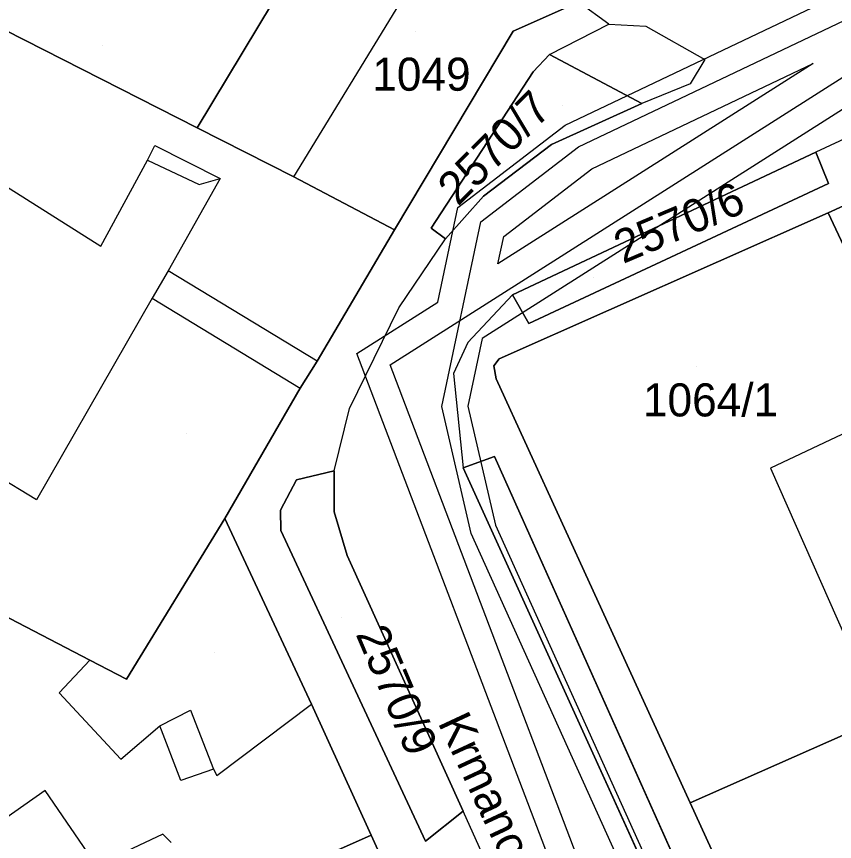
# Model space of a CAD drawing. Extents: x -263423 to -261326, y -1240067 to -1237864.
# Drawn here: x -262616.67 to -262567.2, y -1239776.12 to -1239726.22 of the extents above; entities that cross this region are included whole.
import ezdxf

# ---------------------------------------------------------------- set-up
doc = ezdxf.new("R2010")
doc.units = 0
for name, color, linetype in [('body_kn', 7, 'Continuous'), ('kladpar_druhypozemkov', 7, 'Continuous'), ('kladpar_hranice', 7, 'Continuous'), ('kladpar_parcelnecisla', 7, 'Continuous'), ('kladpar_plochy', 7, 'Continuous'), ('popisy', 7, 'Continuous'), ('tarchy_linie', 7, 'Continuous'), ('zappar_hrandruhpozemk', 7, 'Continuous')]:
    doc.layers.add(name, color=color, linetype=linetype)

msp = doc.modelspace()

# ---------------------------------------------------------------- linework, layer by layer
at = {"layer": 'body_kn'}
for p, q in [((-262580.85, -1239726.69), (-262580.85, -1239726.69)), ((-262586.63, -1239727.11), (-262586.63, -1239727.11)), ((-262578.61, -1239726.8), (-262578.61, -1239726.8)), ((-262584.43, -1239728.52), (-262584.43, -1239728.52)), ((-262584.43, -1239728.52), (-262584.43, -1239728.52)), ((-262575.04, -1239728.82), (-262575.04, -1239728.82)), ((-262568.48, -1239729.06), (-262568.48, -1239729.06)), ((-262585.42, -1239729.57), (-262585.42, -1239729.57)), ((-262575.93, -1239730.29), (-262575.93, -1239730.29)), ((-262578.84, -1239731.48), (-262578.84, -1239731.48)), ((-262605.75, -1239732.95), (-262605.75, -1239732.95)), ((-262583.49, -1239732.79), (-262583.49, -1239732.79)), ((-262608.3, -1239734.02), (-262608.3, -1239734.02)), ((-262584.32, -1239733.97), (-262584.32, -1239733.97)), ((-262582.68, -1239734.11), (-262582.68, -1239734.11)), ((-262568.33, -1239734.43), (-262568.33, -1239734.43)), ((-262608.75, -1239734.91), (-262608.75, -1239734.91)), ((-262608.75, -1239734.91), (-262608.75, -1239734.91)), ((-262581.87, -1239735.43), (-262581.87, -1239735.43)), ((-262604.36, -1239736.02), (-262604.36, -1239736.02)), ((-262599.9, -1239735.91), (-262599.9, -1239735.91)), ((-262599.9, -1239735.91), (-262599.9, -1239735.91)), ((-262605.63, -1239736.39), (-262605.63, -1239736.39)), ((-262567.56, -1239736.33), (-262567.56, -1239736.33)), ((-262588.43, -1239737.08), (-262588.43, -1239737.08)), ((-262589.98, -1239737.78), (-262589.98, -1239737.78)), ((-262567.58, -1239738.09), (-262567.58, -1239738.09)), ((-262567.58, -1239738.09), (-262567.58, -1239738.09)), ((-262588.59, -1239738.65), (-262588.59, -1239738.65)), ((-262593.8, -1239739.12), (-262593.8, -1239739.12)), ((-262591.59, -1239739.02), (-262591.59, -1239739.02)), ((-262590.73, -1239739.67), (-262590.73, -1239739.67)), ((-262587.2, -1239739.52), (-262587.2, -1239739.52)), ((-262611.57, -1239740.12), (-262611.57, -1239740.12)), ((-262587.55, -1239741.18), (-262587.55, -1239741.18)), ((-262587.55, -1239741.18), (-262587.55, -1239741.18)), ((-262607.5, -1239741.61), (-262607.5, -1239741.61)), ((-262586.67, -1239743.05), (-262586.67, -1239743.05)), ((-262586.67, -1239743.05), (-262586.67, -1239743.05)), ((-262608.46, -1239743.26), (-262608.46, -1239743.26)), ((-262591.19, -1239743.49), (-262591.19, -1239743.49)), ((-262593.54, -1239743.84), (-262593.54, -1239743.84)), ((-262585.68, -1239744.78), (-262585.68, -1239744.78)), ((-262588.51, -1239745.7), (-262588.51, -1239745.7)), ((-262589.37, -1239745.93), (-262589.37, -1239745.93)), ((-262596.09, -1239746.61), (-262596.09, -1239746.61)), ((-262598.48, -1239747.06), (-262598.48, -1239747.06)), ((-262598.48, -1239747.06), (-262598.48, -1239747.06)), ((-262587.47, -1239746.92), (-262587.47, -1239746.92)), ((-262594.07, -1239747.28), (-262594.07, -1239747.28)), ((-262587.79, -1239747.36), (-262587.79, -1239747.36)), ((-262590.24, -1239747.81), (-262590.24, -1239747.81)), ((-262587.66, -1239748.13), (-262587.66, -1239748.13)), ((-262599.51, -1239748.71), (-262599.51, -1239748.71)), ((-262596.53, -1239749.94), (-262596.53, -1239749.94)), ((-262590.95, -1239749.81), (-262590.95, -1239749.81)), ((-262589.37, -1239749.79), (-262589.37, -1239749.79)), ((-262587.75, -1239752.83), (-262587.75, -1239752.83)), ((-262597.45, -1239753.7), (-262597.45, -1239753.7)), ((-262597.45, -1239753.7), (-262597.45, -1239753.7)), ((-262589.66, -1239753.52), (-262589.66, -1239753.52)), ((-262589.66, -1239753.52), (-262589.66, -1239753.52)), ((-262571.07, -1239753.55), (-262571.07, -1239753.55)), ((-262599.73, -1239754.24), (-262599.73, -1239754.24)), ((-262615.45, -1239755.46), (-262615.45, -1239755.46)), ((-262600.71, -1239756.09), (-262600.71, -1239756.09)), ((-262597.46, -1239756.18), (-262597.46, -1239756.18)), ((-262604.06, -1239756.59), (-262604.06, -1239756.59)), ((-262587.69, -1239756.99), (-262587.69, -1239756.99)), ((-262600.68, -1239757.32), (-262600.68, -1239757.32)), ((-262589.16, -1239757.49), (-262589.16, -1239757.49)), ((-262596.66, -1239758.83), (-262596.66, -1239758.83)), ((-262612.24, -1239765.15), (-262612.24, -1239765.15)), ((-262612.24, -1239765.15), (-262612.24, -1239765.15)), ((-262610.01, -1239766.31), (-262610.01, -1239766.31)), ((-262614.09, -1239767.12), (-262614.09, -1239767.12)), ((-262606.14, -1239768.17), (-262606.14, -1239768.17)), ((-262598.82, -1239767.82), (-262598.82, -1239767.82)), ((-262607.99, -1239769.12), (-262607.99, -1239769.12)), ((-262610.35, -1239771.15), (-262610.35, -1239771.15)), ((-262604.75, -1239771.75), (-262604.75, -1239771.75)), ((-262604.75, -1239771.75), (-262604.75, -1239771.75)), ((-262604.56, -1239772.13), (-262604.56, -1239772.13)), ((-262606.73, -1239772.44), (-262606.73, -1239772.44)), ((-262614.94, -1239773.04), (-262614.94, -1239773.04)), ((-262575.93, -1239773.78), (-262575.93, -1239773.78)), ((-262589.66, -1239774.29), (-262589.66, -1239774.29)), ((-262607.82, -1239775.68), (-262607.82, -1239775.68)), ((-262595.22, -1239775.74), (-262595.22, -1239775.74)), ((-262591.93, -1239776.1), (-262591.93, -1239776.1))]:
    msp.add_line(p, q, dxfattribs=at)
at = {"layer": 'kladpar_druhypozemkov'}
for p, q in [((-262592.52, -1239727.11), (-262592.52, -1239727.11)), ((-262611.48, -1239727.97), (-262611.48, -1239727.97)), ((-262583.67, -1239731.6), (-262583.67, -1239731.6)), ((-262581.79, -1239741.99), (-262581.79, -1239741.99)), ((-262575.52, -1239747.41), (-262575.52, -1239747.41)), ((-262606.38, -1239751.47), (-262606.38, -1239751.47)), ((-262596.99, -1239762.57), (-262596.99, -1239762.57)), ((-262604.68, -1239764.67), (-262604.68, -1239764.67)), ((-262578.7, -1239776.06), (-262578.7, -1239776.06))]:
    msp.add_line(p, q, dxfattribs=at)
at = {"layer": 'kladpar_hranice'}
for points in [[(-262451.68, -1239667.17), (-262451.23, -1239668.28), (-262460.7, -1239672.48), (-262459.45, -1239675.31), (-262450.08, -1239671.04), (-262449.88, -1239671.51), (-262445.64, -1239681.71), (-262444.85, -1239683.55), (-262470.85, -1239694.98), (-262473.53, -1239696.16), (-262490.19, -1239703.49), (-262516.65, -1239715.13), (-262520.79, -1239716.96), (-262535.01, -1239723.27), (-262548.9, -1239729.45), (-262556.42, -1239732.92), (-262556.62, -1239733.02), (-262559.29, -1239734.31), (-262559.85, -1239734.56), (-262567.58, -1239738.09)], [(-262586.63, -1239727.11), (-262582.68, -1239725.35), (-262578.09, -1239723.27), (-262558.66, -1239714.51), (-262552.49, -1239711.73), (-262529.26, -1239701.26), (-262527.35, -1239700.25), (-262522.32, -1239697.89), (-262517.4, -1239695.64)], [(-262596.33, -1239717.39), (-262598, -1239720.19), (-262600.24, -1239723.81), (-262605.75, -1239732.95), (-262622.01, -1239724.66), (-262626.2, -1239722.48), (-262626.46, -1239722.8), (-262634.27, -1239717.98), (-262626.07, -1239705.15), (-262622.39, -1239708.04), (-262619.83, -1239704.16), (-262596.33, -1239717.39)], [(-262591.12, -1239720.34), (-262583.18, -1239724.9), (-262582.68, -1239725.35), (-262586.63, -1239727.11), (-262593.8, -1239739.12), (-262599.9, -1239735.91), (-262605.75, -1239732.95), (-262600.24, -1239723.81), (-262598, -1239720.19), (-262596.33, -1239717.39), (-262591.12, -1239720.34)], [(-262634.27, -1239717.98), (-262626.46, -1239722.8), (-262626.2, -1239722.48), (-262622.01, -1239724.66), (-262605.75, -1239732.95), (-262599.9, -1239735.91), (-262593.8, -1239739.12), (-262598.48, -1239747.06), (-262599.51, -1239748.71), (-262604.06, -1239756.59), (-262610.01, -1239766.31), (-262612.24, -1239765.15), (-262619.03, -1239761.62), (-262624.31, -1239758.73), (-262639.86, -1239747.9), (-262649, -1239741.36), (-262648.81, -1239741.1), (-262648.49, -1239740.53), (-262643.94, -1239732.97), (-262641, -1239728.65), (-262638.63, -1239724.97), (-262634.27, -1239717.98)], [(-262587.66, -1239748.13), (-262575.93, -1239773.78), (-262560.41, -1239807.74), (-262562.89, -1239808.81), (-262563.41, -1239809.03), (-262563, -1239808.14), (-262566.99, -1239799.19), (-262568.5, -1239800.1), (-262565.39, -1239806.94), (-262563.41, -1239809.03), (-262572.52, -1239812.91), (-262586.96, -1239780.25), (-262589.76, -1239780.87), (-262575.06, -1239814.02), (-262575.26, -1239814.11), (-262577.3, -1239815.05), (-262592.7, -1239781.29), (-262595.22, -1239775.74), (-262598.82, -1239767.82), (-262604.06, -1239756.59), (-262599.51, -1239748.71), (-262598.48, -1239747.06), (-262593.8, -1239739.12), (-262586.63, -1239727.11)], [(-262584.43, -1239728.52), (-262585.42, -1239729.57), (-262591.59, -1239739.02), (-262590.73, -1239739.67), (-262588.43, -1239737.08), (-262584.32, -1239733.97), (-262578.84, -1239731.48), (-262584.43, -1239728.52)], [(-262584.43, -1239728.52), (-262578.84, -1239731.48), (-262584.32, -1239733.97), (-262588.43, -1239737.08), (-262590.73, -1239739.67), (-262591.59, -1239739.02), (-262585.42, -1239729.57), (-262584.43, -1239728.52)], [(-262548.9, -1239729.45), (-262543.84, -1239740.6), (-262541.33, -1239746.12), (-262547.15, -1239748.9), (-262549.86, -1239743.5), (-262551.49, -1239744.25), (-262554.73, -1239745.79), (-262560.4, -1239748.49), (-262562.28, -1239749.39), (-262567.58, -1239738.09), (-262559.85, -1239734.56), (-262559.29, -1239734.31), (-262556.62, -1239733.02), (-262556.42, -1239732.92), (-262548.9, -1239729.45)], [(-262586.67, -1239743.05), (-262568.33, -1239734.43), (-262567.56, -1239736.33), (-262585.68, -1239744.78), (-262586.67, -1239743.05)], [(-262567.56, -1239736.33), (-262568.33, -1239734.43), (-262586.67, -1239743.05), (-262585.68, -1239744.78), (-262567.56, -1239736.33)], [(-262567.58, -1239738.09), (-262562.28, -1239749.39), (-262560.44, -1239753.47), (-262559.42, -1239755.72), (-262558.18, -1239758.45), (-262560.98, -1239759.65), (-262563.78, -1239760.84), (-262561.2, -1239766.72), (-262561.01, -1239767.16), (-262562.73, -1239767.92), (-262564.39, -1239768.68), (-262575.93, -1239773.78), (-262587.66, -1239748.13), (-262587.79, -1239747.36), (-262587.47, -1239746.92), (-262567.58, -1239738.09)], [(-262567.58, -1239738.09), (-262587.47, -1239746.92), (-262587.79, -1239747.36), (-262587.66, -1239748.13)], [(-262639.86, -1239747.9), (-262624.31, -1239758.73), (-262619.03, -1239761.62), (-262612.24, -1239765.15), (-262610.01, -1239766.31), (-262604.06, -1239756.59), (-262598.82, -1239767.82), (-262595.22, -1239775.74), (-262605.55, -1239780.34), (-262611.8, -1239783.18), (-262613.56, -1239778.91), (-262624.67, -1239786.69), (-262630.98, -1239772.46), (-262636.99, -1239776.45), (-262637.25, -1239776.16), (-262642.89, -1239769.76), (-262650.86, -1239760.42), (-262651.32, -1239760.8), (-262658.15, -1239752.53), (-262650.16, -1239743.07), (-262649, -1239741.36), (-262639.86, -1239747.9)], [(-262589.66, -1239753.52), (-262587.75, -1239752.83), (-262569.41, -1239793.81), (-262570, -1239794.14), (-262567.84, -1239798.75), (-262568.85, -1239799.31), (-262589.66, -1239753.52)], [(-262587.75, -1239752.83), (-262589.66, -1239753.52), (-262568.85, -1239799.31), (-262567.84, -1239798.75), (-262570, -1239794.14), (-262569.41, -1239793.81), (-262587.75, -1239752.83)], [(-262597.45, -1239753.7), (-262597.46, -1239756.18), (-262596.66, -1239758.83), (-262589.66, -1239774.29), (-262591.93, -1239776.1), (-262600.68, -1239757.32), (-262600.71, -1239756.09), (-262599.73, -1239754.24), (-262597.45, -1239753.7)], [(-262599.73, -1239754.24), (-262600.71, -1239756.09), (-262600.68, -1239757.32), (-262591.93, -1239776.1), (-262589.66, -1239774.29), (-262596.66, -1239758.83), (-262597.46, -1239756.18), (-262597.45, -1239753.7), (-262599.73, -1239754.24)], [(-262564.39, -1239768.68), (-262562.73, -1239767.92), (-262561.01, -1239767.16), (-262558.14, -1239765.9), (-262555.27, -1239764.64), (-262555.08, -1239765.09), (-262546.38, -1239785), (-262540.33, -1239798.65), (-262560.41, -1239807.74), (-262575.93, -1239773.78), (-262564.39, -1239768.68)], [(-262592.7, -1239781.29), (-262577.3, -1239815.05), (-262595.03, -1239823), (-262601.08, -1239808.52), (-262609.4, -1239788.8), (-262611.8, -1239783.18), (-262605.55, -1239780.34), (-262595.22, -1239775.74), (-262592.7, -1239781.29)]]:
    msp.add_lwpolyline(points, dxfattribs=at)
at = {"layer": 'kladpar_plochy'}
for p, q in [((-262586.63, -1239727.11), (-262582.68, -1239725.35)), ((-262593.8, -1239739.12), (-262586.63, -1239727.11)), ((-262584.43, -1239728.52), (-262585.42, -1239729.57)), ((-262578.84, -1239731.48), (-262584.43, -1239728.52)), ((-262585.42, -1239729.57), (-262591.59, -1239739.02)), ((-262584.32, -1239733.97), (-262578.84, -1239731.48)), ((-262588.43, -1239737.08), (-262584.32, -1239733.97)), ((-262568.33, -1239734.43), (-262586.67, -1239743.05)), ((-262567.56, -1239736.33), (-262568.33, -1239734.43)), ((-262559.85, -1239734.56), (-262567.58, -1239738.09)), ((-262585.68, -1239744.78), (-262567.56, -1239736.33)), ((-262590.73, -1239739.67), (-262588.43, -1239737.08)), ((-262567.58, -1239738.09), (-262587.47, -1239746.92)), ((-262598.48, -1239747.06), (-262593.8, -1239739.12)), ((-262591.59, -1239739.02), (-262590.73, -1239739.67)), ((-262586.67, -1239743.05), (-262585.68, -1239744.78)), ((-262599.51, -1239748.71), (-262598.48, -1239747.06)), ((-262587.47, -1239746.92), (-262587.79, -1239747.36)), ((-262587.79, -1239747.36), (-262587.66, -1239748.13)), ((-262587.66, -1239748.13), (-262575.93, -1239773.78)), ((-262604.06, -1239756.59), (-262599.51, -1239748.71)), ((-262587.75, -1239752.83), (-262589.66, -1239753.52)), ((-262569.41, -1239793.81), (-262587.75, -1239752.83)), ((-262597.45, -1239753.7), (-262599.73, -1239754.24)), ((-262597.46, -1239756.18), (-262597.45, -1239753.7)), ((-262589.66, -1239753.52), (-262568.85, -1239799.31)), ((-262599.73, -1239754.24), (-262600.71, -1239756.09)), ((-262600.71, -1239756.09), (-262600.68, -1239757.32)), ((-262596.66, -1239758.83), (-262597.46, -1239756.18)), ((-262598.82, -1239767.82), (-262604.06, -1239756.59)), ((-262600.68, -1239757.32), (-262591.93, -1239776.1)), ((-262589.66, -1239774.29), (-262596.66, -1239758.83)), ((-262595.22, -1239775.74), (-262598.82, -1239767.82)), ((-262575.93, -1239773.78), (-262560.41, -1239807.74)), ((-262591.93, -1239776.1), (-262589.66, -1239774.29)), ((-262592.7, -1239781.29), (-262595.22, -1239775.74))]:
    msp.add_line(p, q, dxfattribs=at)
for points in [[(-262596.33, -1239717.39), (-262598, -1239720.19), (-262600.24, -1239723.81), (-262605.75, -1239732.95), (-262622.01, -1239724.66), (-262626.2, -1239722.48), (-262626.46, -1239722.8), (-262634.27, -1239717.98), (-262626.07, -1239705.15), (-262622.39, -1239708.04), (-262619.83, -1239704.16)], [(-262591.12, -1239720.34), (-262583.18, -1239724.9), (-262582.68, -1239725.35), (-262586.63, -1239727.11), (-262593.8, -1239739.12), (-262599.9, -1239735.91), (-262605.75, -1239732.95), (-262600.24, -1239723.81), (-262598, -1239720.19), (-262596.33, -1239717.39)], [(-262634.27, -1239717.98), (-262626.46, -1239722.8), (-262626.2, -1239722.48), (-262622.01, -1239724.66), (-262605.75, -1239732.95), (-262599.9, -1239735.91), (-262593.8, -1239739.12), (-262598.48, -1239747.06), (-262599.51, -1239748.71), (-262604.06, -1239756.59), (-262610.01, -1239766.31), (-262612.24, -1239765.15), (-262619.03, -1239761.62), (-262624.31, -1239758.73), (-262639.86, -1239747.9), (-262649, -1239741.36), (-262648.81, -1239741.1), (-262648.49, -1239740.53), (-262643.94, -1239732.97), (-262641, -1239728.65), (-262638.63, -1239724.97)], [(-262584.43, -1239728.52), (-262578.84, -1239731.48), (-262584.32, -1239733.97), (-262588.43, -1239737.08), (-262590.73, -1239739.67), (-262591.59, -1239739.02), (-262585.42, -1239729.57)], [(-262548.9, -1239729.45), (-262543.84, -1239740.6), (-262541.33, -1239746.12), (-262547.15, -1239748.9), (-262549.86, -1239743.5), (-262551.49, -1239744.25), (-262554.73, -1239745.79), (-262560.4, -1239748.49), (-262562.28, -1239749.39), (-262567.58, -1239738.09), (-262559.85, -1239734.56), (-262559.29, -1239734.31), (-262556.62, -1239733.02), (-262556.42, -1239732.92)], [(-262586.67, -1239743.05), (-262568.33, -1239734.43), (-262567.56, -1239736.33), (-262585.68, -1239744.78)], [(-262567.58, -1239738.09), (-262562.28, -1239749.39), (-262560.44, -1239753.47), (-262559.42, -1239755.72), (-262558.18, -1239758.45), (-262560.98, -1239759.65), (-262563.78, -1239760.84), (-262561.2, -1239766.72), (-262561.01, -1239767.16), (-262562.73, -1239767.92), (-262564.39, -1239768.68), (-262575.93, -1239773.78), (-262587.66, -1239748.13), (-262587.79, -1239747.36), (-262587.47, -1239746.92)], [(-262639.86, -1239747.9), (-262624.31, -1239758.73), (-262619.03, -1239761.62), (-262612.24, -1239765.15), (-262610.01, -1239766.31), (-262604.06, -1239756.59), (-262598.82, -1239767.82), (-262595.22, -1239775.74), (-262605.55, -1239780.34), (-262611.8, -1239783.18), (-262613.56, -1239778.91), (-262624.67, -1239786.69), (-262630.98, -1239772.46), (-262636.99, -1239776.45), (-262637.25, -1239776.16), (-262642.89, -1239769.76), (-262650.86, -1239760.42), (-262651.32, -1239760.8), (-262658.15, -1239752.53), (-262650.16, -1239743.07), (-262649, -1239741.36)], [(-262589.66, -1239753.52), (-262587.75, -1239752.83), (-262569.41, -1239793.81), (-262570, -1239794.14), (-262567.84, -1239798.75), (-262568.85, -1239799.31)], [(-262597.45, -1239753.7), (-262597.46, -1239756.18), (-262596.66, -1239758.83), (-262589.66, -1239774.29), (-262591.93, -1239776.1), (-262600.68, -1239757.32), (-262600.71, -1239756.09), (-262599.73, -1239754.24)], [(-262564.39, -1239768.68), (-262562.73, -1239767.92), (-262561.01, -1239767.16), (-262558.14, -1239765.9), (-262555.27, -1239764.64), (-262555.08, -1239765.09), (-262546.38, -1239785), (-262540.33, -1239798.65), (-262560.41, -1239807.74), (-262575.93, -1239773.78)], [(-262592.7, -1239781.29), (-262577.3, -1239815.05), (-262595.03, -1239823), (-262601.08, -1239808.52), (-262609.4, -1239788.8), (-262611.8, -1239783.18), (-262605.55, -1239780.34), (-262595.22, -1239775.74)]]:
    msp.add_lwpolyline(points, close=True, dxfattribs=at)
at = {"layer": 'tarchy_linie'}
for points in [[(-262591.74, -1239826.65), (-262565.09, -1239814.55), (-262567.95, -1239808.22), (-262570.42, -1239809.3), (-262584.34, -1239777.5), (-262596.09, -1239746.61), (-262591.19, -1239743.49), (-262589.98, -1239737.78), (-262583.49, -1239732.79), (-262517.03, -1239701.16), (-262561.83, -1239685.92), (-262610.93, -1239668.94), (-262610.64, -1239668.32), (-262609.75, -1239668.08), (-262609.89, -1239667.55), (-262610.03, -1239667.05), (-262609.65, -1239666.28), (-262608.97, -1239664.88), (-262599.91, -1239667.71), (-262511.91, -1239698.73)], [(-262563.05, -1239815.33), (-262589.16, -1239757.49), (-262590.95, -1239749.81), (-262588.59, -1239738.65), (-262582.68, -1239734.11), (-262511.84, -1239700.39), (-262476.21, -1239684.42), (-262449.67, -1239672.01)], [(-262569.51, -1239807.26), (-262582.81, -1239776.88), (-262594.07, -1239747.28), (-262557.61, -1239724.1), (-262509.31, -1239702.04), (-262475.06, -1239686.29), (-262448.71, -1239674.33)], [(-262508.62, -1239703.54), (-262556.82, -1239725.55), (-262588.51, -1239745.7), (-262589.37, -1239749.79), (-262587.69, -1239756.99), (-262562.28, -1239813.3), (-262498.48, -1239785.44)], [(-262587.55, -1239741.18), (-262587.2, -1239739.52), (-262581.87, -1239735.43), (-262568.48, -1239729.06), (-262587.55, -1239741.18)]]:
    msp.add_lwpolyline(points, dxfattribs=at)
at = {"layer": 'zappar_hrandruhpozemk'}
for p, q in [((-262599.9, -1239735.91), (-262592.41, -1239723.65)), ((-262580.85, -1239726.69), (-262582.68, -1239725.35)), ((-262584.43, -1239728.52), (-262580.85, -1239726.69)), ((-262575.04, -1239728.82), (-262575.93, -1239730.29)), ((-262575.93, -1239730.29), (-262578.84, -1239731.48)), ((-262560.76, -1239730.9), (-262568.33, -1239734.43)), ((-262608.75, -1239734.91), (-262605.63, -1239736.39)), ((-262605.63, -1239736.39), (-262604.36, -1239736.02)), ((-262598.48, -1239747.06), (-262607.5, -1239741.61)), ((-262586.67, -1239743.05), (-262589.37, -1239745.93)), ((-262608.46, -1239743.26), (-262615.45, -1239755.46)), ((-262608.46, -1239743.26), (-262599.51, -1239748.71)), ((-262562.28, -1239749.39), (-262571.07, -1239753.55)), ((-262597.45, -1239753.7), (-262596.53, -1239749.94)), ((-262571.07, -1239753.55), (-262564.58, -1239768.23)), ((-262612.24, -1239765.15), (-262614.09, -1239767.12)), ((-262614.09, -1239767.12), (-262610.35, -1239771.15)), ((-262604.56, -1239772.13), (-262598.82, -1239767.82)), ((-262606.73, -1239772.44), (-262607.99, -1239769.12)), ((-262604.75, -1239771.75), (-262606.73, -1239772.44)), ((-262586.96, -1239780.25), (-262589.66, -1239774.29))]:
    msp.add_line(p, q, dxfattribs=at)
for points in [[(-262580.85, -1239726.69), (-262578.61, -1239726.8), (-262575.04, -1239728.82)], [(-262629.04, -1239731), (-262628.2, -1239729.6), (-262611.57, -1239740.12), (-262608.75, -1239734.91), (-262608.3, -1239734.02), (-262604.36, -1239736.02), (-262607.5, -1239741.61), (-262608.46, -1239743.26)], [(-262596.53, -1239749.94), (-262593.54, -1239743.84), (-262590.73, -1239739.67)], [(-262589.37, -1239745.93), (-262590.24, -1239747.81), (-262589.66, -1239753.52)], [(-262615.45, -1239755.46), (-262617.99, -1239753.92), (-262619.14, -1239755.57), (-262622.82, -1239753.2), (-262625.13, -1239757.01), (-262626.15, -1239756.94)], [(-262610.35, -1239771.15), (-262607.99, -1239769.12), (-262606.14, -1239768.17), (-262604.75, -1239771.75), (-262604.56, -1239772.13)], [(-262607.31, -1239776.19), (-262607.82, -1239775.68), (-262611.84, -1239777.58), (-262614.94, -1239773.04), (-262619.92, -1239776.52), (-262620.49, -1239776.71), (-262621.26, -1239776.71), (-262621.96, -1239776.32)]]:
    msp.add_lwpolyline(points, dxfattribs=at)

# ---------------------------------------------------------------- texts
at = {"layer": 'kladpar_parcelnecisla'}
for s, p in [('1049', (-262595.152, -1239730.71)), ('1064/1', (-262578.782, -1239750.41))]:
    msp.add_text(s, height=2, dxfattribs=at).set_placement(p)
for s, rotation, p in [('2570/7', 45, (-262589.968, -1239737.732)), ('2570/6', 23, (-262579.98, -1239741.195)), ('2570/9', 293, (-262596.175, -1239763.57))]:
    msp.add_text(s, height=2, rotation=rotation, dxfattribs=at).set_placement(p)
at = {"layer": 'popisy'}
msp.add_text('Krmanova', height=2, rotation=295, dxfattribs=at).set_placement((-262591.209, -1239768.924))

doc.saveas('drawing.dxf')
